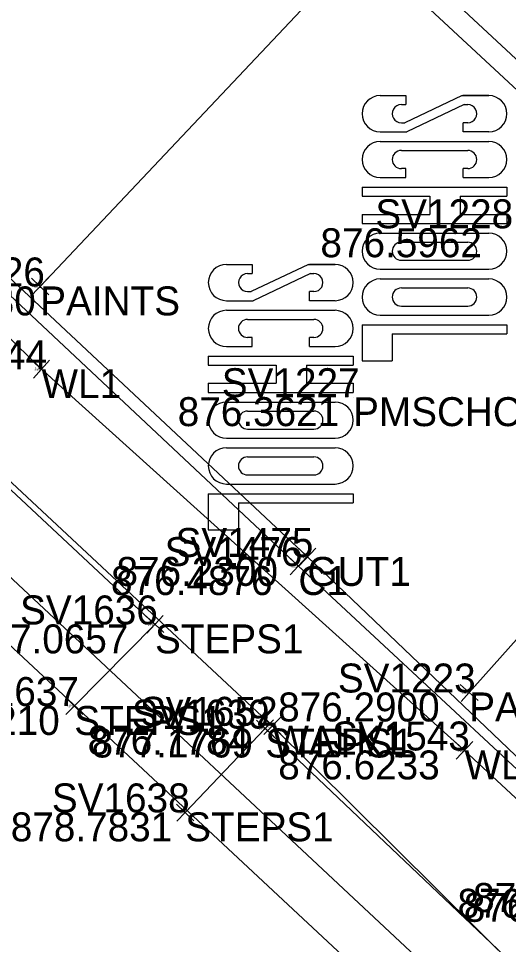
# Model space of a CAD drawing. Extents: x 1469677 to 1493262, y 375219 to 389293.
# Drawn here: x 1480273.43 to 1480293.74, y 379275.14 to 379313.52 of the extents above; entities that cross this region are included whole.
import ezdxf

# ---------------------------------------------------------------- set-up
doc = ezdxf.new("R2010")
doc.units = 0
for name, color, linetype in [('Building', 7, 'Continuous'), ('DR_X_Drive_Pipe', 7, 'Continuous'), ('DV_X_Lot_Line', 7, 'Continuous'), ('DV_X_Text', 7, 'Continuous'), ('GK_Visualization', 7, 'Continuous'), ('PNTELEV', 7, 'Continuous'), ('Property', 7, 'Continuous'), ('RD_P_Text', 7, 'Continuous'), ('RW_P_Esmt_SW', 7, 'Continuous'), ('RW_P_Esmt_TMP', 7, 'Continuous'), ('SV_X_Mon_Cells_Found', 7, 'Continuous'), ('SV_X_Text', 7, 'Continuous'), ('SV_X_Text_Elevation', 7, 'Continuous'), ('Text Street', 7, 'Continuous')]:
    doc.layers.add(name, color=color, linetype=linetype)

msp = doc.modelspace()

# ---------------------------------------------------------------- linework, layer by layer
at = {"layer": 'Building'}
msp.add_lwpolyline([(1480349.171, 379259.048), (1480326.954, 379280.06), (1480305.568, 379299.916), (1480284.393, 379319.578), (1480263.301, 379339.268), (1480242.575, 379359.213), (1480224.612, 379376.165), (1480208.191, 379391.527)], dxfattribs=at)
at = {"layer": 'DR_X_Drive_Pipe'}
msp.add_lwpolyline([(1480327.263, 379249.797), (1480312.798, 379263.799), (1480291.915, 379283.182), (1480274.385, 379298.987), (1480265.401, 379307.725), (1480264.495, 379308.458), (1480240.472, 379331.084), (1480234.677, 379335.863), (1480225.088, 379345.601), (1480208.322, 379361.342), (1480207.346, 379362.25), (1480199.528, 379369.768), (1480193.21, 379375.651), (1480182.823, 379385.139), (1480177.927, 379389.525), (1480169.423, 379398.321), (1480161.035, 379406.189), (1480144.924, 379421.019), (1480134.739, 379430.559), (1480121.485, 379441.998)], dxfattribs=at)
at = {"layer": 'DV_X_Lot_Line'}
msp.add_lwpolyline([(1480327.959, 379242.083), (1480313.163, 379256.356), (1480297.576, 379270.674), (1480283.951, 379284.205), (1480267.344, 379299.69), (1480258.509, 379307.782), (1480244.036, 379321.372), (1480229.243, 379335.021), (1480213.414, 379349.982), (1480196.806, 379366.202), (1480192.296, 379370.271), (1480186.385, 379375.802), (1480181.8, 379379.27), (1480179.258, 379381.212), (1480177.445, 379382.131), (1480174.921, 379382.868), (1480171.98, 379383.537), (1480169.491, 379383.403), (1480167.014, 379382.902), (1480162.891, 379380.83), (1480161.298, 379379.691), (1480158.915, 379377.808)], dxfattribs=at)
at = {"layer": 'PNTELEV'}
for p, q in [((1480274.675, 379302.78), (1480273.989, 379302.052)), ((1480274.696, 379302.073), (1480273.968, 379302.759)), ((1480274.332, 379302.416), (1480274.332, 379302.416)), ((1480274.757, 379298.652), (1480274.014, 379299.322)), ((1480274.05, 379298.616), (1480274.72, 379299.358)), ((1480274.385, 379298.987), (1480274.385, 379298.987)), ((1480285.771, 379290.857), (1480285.048, 379291.548)), ((1480285.064, 379290.841), (1480285.755, 379291.564)), ((1480285.399, 379290.486), (1480284.667, 379291.167)), ((1480284.693, 379290.46), (1480285.374, 379291.192)), ((1480285.409, 379291.203), (1480285.409, 379291.203)), ((1480285.033, 379290.826), (1480285.033, 379290.826)), ((1480278.723, 379288.748), (1480279.455, 379288.066)), ((1480279.43, 379288.773), (1480278.748, 379288.042)), ((1480279.089, 379288.407), (1480279.089, 379288.407)), ((1480291.737, 379285.918), (1480292.482, 379285.252)), ((1480291.776, 379285.212), (1480292.443, 379285.958)), ((1480292.11, 379285.585), (1480292.11, 379285.585)), ((1480276.098, 379284.673), (1480275.388, 379285.376)), ((1480276.095, 379285.38), (1480275.391, 379284.669)), ((1480275.743, 379285.025), (1480275.743, 379285.025)), ((1480283.297, 379284.436), (1480284.021, 379283.745)), ((1480283.314, 379283.729), (1480284.004, 379284.452)), ((1480284.306, 379283.852), (1480283.596, 379284.557)), ((1480283.599, 379283.85), (1480284.303, 379284.56)), ((1480283.659, 379284.091), (1480283.659, 379284.091)), ((1480283.951, 379284.205), (1480283.951, 379284.205)), ((1480292.282, 379282.842), (1480291.549, 379283.522)), ((1480291.575, 379282.816), (1480292.255, 379283.548)), ((1480291.915, 379283.182), (1480291.915, 379283.182)), ((1480279.979, 379280.961), (1480280.703, 379280.271)), ((1480279.996, 379280.254), (1480280.686, 379280.977)), ((1480280.341, 379280.616), (1480280.341, 379280.616))]:
    msp.add_line(p, q, dxfattribs=at)
at = {"layer": 'Property'}
for points in [[(1480263.984, 379296.161), (1480267.157, 379299.539), (1480279.089, 379288.407), (1480275.743, 379285.025)], [(1480280.341, 379280.616), (1480283.659, 379284.091), (1480295.222, 379273.109), (1480291.804, 379269.54)]]:
    msp.add_lwpolyline(points, dxfattribs=at)
at = {"layer": 'RD_P_Text'}
for points in [[(1480328.343, 379250.587), (1480312.97, 379265.236), (1480299.564, 379277.688), (1480285.409, 379291.203), (1480266.888, 379308.553), (1480264.304, 379310.926), (1480249.8, 379324.506)], [(1480327.862, 379250.385), (1480312.733, 379264.825), (1480299.577, 379277.28), (1480299.42, 379277.447), (1480285.033, 379290.826), (1480266.518, 379308.208), (1480264.058, 379310.698), (1480249.543, 379324.24)]]:
    msp.add_lwpolyline(points, dxfattribs=at)
at = {"layer": 'RW_P_Esmt_TMP'}
for p, q in [((1480288.423, 379310.327), (1480289.485, 379310.327)), ((1480291.818, 379310.327), (1480289.443, 379309.202)), ((1480289.485, 379310.327), (1480289.485, 379309.952)), ((1480291.818, 379310.327), (1480292.923, 379310.327)), ((1480292.923, 379310.327), (1480291.86, 379310.327)), ((1480289.298, 379309.952), (1480289.485, 379309.952)), ((1480291.902, 379309.952), (1480289.527, 379308.827)), ((1480291.902, 379309.952), (1480292.048, 379309.952)), ((1480289.298, 379309.202), (1480289.443, 379309.202)), ((1480292.048, 379309.202), (1480291.86, 379309.202)), ((1480291.86, 379308.827), (1480291.86, 379309.202)), ((1480288.423, 379308.827), (1480289.527, 379308.827)), ((1480292.923, 379308.827), (1480291.86, 379308.827)), ((1480288.423, 379308.427), (1480292.923, 379308.427)), ((1480289.298, 379308.052), (1480292.048, 379308.052)), ((1480289.485, 379307.302), (1480289.298, 379307.302)), ((1480289.485, 379306.927), (1480289.485, 379307.302)), ((1480291.86, 379306.927), (1480291.86, 379307.302)), ((1480292.048, 379307.302), (1480291.86, 379307.302)), ((1480288.423, 379306.927), (1480289.485, 379306.927)), ((1480291.86, 379306.927), (1480292.923, 379306.927)), ((1480287.673, 379306.527), (1480293.673, 379306.527)), ((1480287.673, 379306.527), (1480287.673, 379306.152)), ((1480293.673, 379306.527), (1480293.673, 379306.152)), ((1480287.673, 379306.152), (1480290.485, 379306.152)), ((1480290.485, 379306.152), (1480290.485, 379305.402)), ((1480291.735, 379306.152), (1480291.735, 379305.402)), ((1480291.735, 379306.152), (1480293.673, 379306.152)), ((1480287.673, 379305.402), (1480290.485, 379305.402)), ((1480287.673, 379305.402), (1480287.673, 379305.027)), ((1480291.735, 379305.402), (1480293.673, 379305.402)), ((1480293.673, 379305.402), (1480293.673, 379305.027)), ((1480287.673, 379305.027), (1480293.673, 379305.027)), ((1480287.673, 379304.827), (1480287.673, 379304.827)), ((1480293.673, 379304.827), (1480293.673, 379304.827)), ((1480288.423, 379304.627), (1480292.923, 379304.627)), ((1480289.298, 379304.252), (1480292.048, 379304.252)), ((1480282.049, 379303.326), (1480283.111, 379303.326)), ((1480285.444, 379303.326), (1480283.069, 379302.201)), ((1480283.111, 379303.326), (1480283.111, 379302.951)), ((1480285.444, 379303.326), (1480286.549, 379303.326)), ((1480286.549, 379303.326), (1480285.486, 379303.326)), ((1480289.298, 379303.502), (1480292.048, 379303.502)), ((1480282.924, 379302.951), (1480283.111, 379302.951)), ((1480285.528, 379302.951), (1480283.153, 379301.826)), ((1480285.528, 379302.951), (1480285.674, 379302.951)), ((1480288.423, 379303.127), (1480292.923, 379303.127)), ((1480288.423, 379302.727), (1480292.923, 379302.727)), ((1480282.924, 379302.201), (1480283.069, 379302.201)), ((1480285.674, 379302.201), (1480285.486, 379302.201)), ((1480285.486, 379301.826), (1480285.486, 379302.201)), ((1480289.298, 379302.352), (1480292.048, 379302.352)), ((1480282.049, 379301.826), (1480283.153, 379301.826)), ((1480286.549, 379301.826), (1480285.486, 379301.826)), ((1480282.049, 379301.426), (1480286.549, 379301.426)), ((1480288.423, 379301.227), (1480292.923, 379301.227)), ((1480289.298, 379301.602), (1480292.048, 379301.602)), ((1480282.924, 379301.051), (1480285.674, 379301.051)), ((1480287.673, 379300.827), (1480293.673, 379300.827)), ((1480287.673, 379300.827), (1480287.673, 379299.327)), ((1480293.673, 379300.827), (1480293.673, 379300.452)), ((1480283.111, 379300.301), (1480282.924, 379300.301)), ((1480283.111, 379299.926), (1480283.111, 379300.301)), ((1480285.486, 379299.926), (1480285.486, 379300.301)), ((1480285.674, 379300.301), (1480285.486, 379300.301)), ((1480288.923, 379300.452), (1480293.673, 379300.452)), ((1480288.923, 379300.452), (1480288.923, 379299.327)), ((1480282.049, 379299.926), (1480283.111, 379299.926)), ((1480285.486, 379299.926), (1480286.549, 379299.926)), ((1480281.299, 379299.526), (1480287.299, 379299.526)), ((1480281.299, 379299.526), (1480281.299, 379299.151)), ((1480287.299, 379299.526), (1480287.299, 379299.151)), ((1480287.673, 379299.327), (1480288.923, 379299.327)), ((1480281.299, 379299.151), (1480284.111, 379299.151)), ((1480284.111, 379299.151), (1480284.111, 379298.401)), ((1480285.361, 379299.151), (1480285.361, 379298.401)), ((1480285.361, 379299.151), (1480287.299, 379299.151)), ((1480281.299, 379298.401), (1480284.111, 379298.401)), ((1480281.299, 379298.401), (1480281.299, 379298.026)), ((1480285.361, 379298.401), (1480287.299, 379298.401)), ((1480287.299, 379298.401), (1480287.299, 379298.026)), ((1480281.299, 379298.026), (1480287.299, 379298.026)), ((1480281.299, 379297.826), (1480281.299, 379297.826)), ((1480287.299, 379297.826), (1480287.299, 379297.826)), ((1480282.049, 379297.626), (1480286.549, 379297.626)), ((1480282.924, 379297.251), (1480285.674, 379297.251)), ((1480282.924, 379296.501), (1480285.674, 379296.501)), ((1480282.049, 379296.126), (1480286.549, 379296.126)), ((1480282.049, 379295.726), (1480286.549, 379295.726)), ((1480282.924, 379295.351), (1480285.674, 379295.351)), ((1480282.924, 379294.601), (1480285.674, 379294.601)), ((1480282.049, 379294.226), (1480286.549, 379294.226)), ((1480281.299, 379293.826), (1480287.299, 379293.826)), ((1480281.299, 379293.826), (1480281.299, 379292.326)), ((1480287.299, 379293.826), (1480287.299, 379293.451)), ((1480282.549, 379293.451), (1480287.299, 379293.451)), ((1480282.549, 379293.451), (1480282.549, 379292.326)), ((1480281.299, 379292.326), (1480282.549, 379292.326))]:
    msp.add_line(p, q, dxfattribs=at)
for centre, radius, start, end in [((1480288.423, 379309.577), 0.75, 90, 270), ((1480292.923, 379309.577), 0.75, 270, 90), ((1480289.298, 379309.577), 0.375, 90, 270.0001), ((1480292.048, 379309.577), 0.375, 270, 90.0001), ((1480288.423, 379307.677), 0.75, 90, 269.997), ((1480292.923, 379307.677), 0.75, 270.003, 90), ((1480289.298, 379307.677), 0.375, 90, 269.997), ((1480292.048, 379307.677), 0.375, 270.003, 90), ((1480288.423, 379303.877), 0.75, 90, 269.997), ((1480292.923, 379303.877), 0.75, 270.003, 90), ((1480289.298, 379303.877), 0.375, 90, 269.997), ((1480292.048, 379303.877), 0.375, 270.003, 90), ((1480282.049, 379302.576), 0.75, 90, 270), ((1480286.549, 379302.576), 0.75, 270, 90), ((1480282.924, 379302.576), 0.375, 90, 270.0001), ((1480285.674, 379302.576), 0.375, 270, 90.0001), ((1480288.423, 379301.977), 0.75, 90, 269.997), ((1480292.923, 379301.977), 0.75, 270.003, 90), ((1480289.298, 379301.977), 0.375, 90, 269.997), ((1480292.048, 379301.977), 0.375, 270.003, 90), ((1480282.049, 379300.676), 0.75, 90, 269.997), ((1480286.549, 379300.676), 0.75, 270.003, 90), ((1480282.924, 379300.676), 0.375, 90, 269.997), ((1480285.674, 379300.676), 0.375, 270.003, 90), ((1480282.049, 379296.876), 0.75, 90, 269.997), ((1480286.549, 379296.876), 0.75, 270.003, 90), ((1480282.924, 379296.876), 0.375, 90, 269.997), ((1480285.674, 379296.876), 0.375, 270.003, 90), ((1480282.049, 379294.976), 0.75, 90, 269.997), ((1480286.549, 379294.976), 0.75, 270.003, 90), ((1480282.924, 379294.976), 0.375, 90, 269.997), ((1480285.674, 379294.976), 0.375, 270.003, 90)]:
    msp.add_arc(centre, radius, start, end, dxfattribs=at)
at = {"layer": 'SV_X_Mon_Cells_Found'}
msp.add_lwpolyline([(1477164.629, 382297.849), (1479615.888, 379904.59), (1480413.414, 379159.216)], dxfattribs=at)
at = {"layer": 'SV_X_Text'}
for points in [[(1480287.258, 379316.117), (1480274.332, 379302.416)], [(1480292.11, 379285.585), (1480304.569, 379299.538)]]:
    msp.add_lwpolyline(points, dxfattribs=at)
at = {"layer": 'SV_X_Text_Elevation'}
msp.add_line((1479636.611, 379926.284), (1480557.828, 379065.308), dxfattribs=at)
at = {"layer": 'Text Street'}
msp.add_lwpolyline([(1480285.873, 379260.463), (1480292.461, 379269.459), (1480263.894, 379296.102), (1480254.759, 379289.34)], dxfattribs=at)

# ---------------------------------------------------------------- texts
at = {"layer": 'DV_X_Text'}
for s, height, p in [('876.5962', 1.2, (1480285.944, 379303.627)), ('876.1130', 1.2, (1480267.455, 379301.216)), ('876.11', 0.06, (1480274.097, 379302.356)), ('876.47', 0.06, (1480274.103, 379298.927)), ('876.3621', 1.2, (1480280.031, 379296.626)), ('876.2300', 1.2, (1480277.492, 379290.003)), ('876.23', 0.06, (1480285.129, 379291.143)), ('876.4876', 1.2, (1480277.267, 379289.626)), ('876.49', 0.06, (1480284.751, 379290.766)), ('877.0657', 1.2, (1480271.294, 379287.207)), ('877.07', 0.06, (1480278.804, 379288.347)), ('876.2900', 1.2, (1480284.192, 379284.385)), ('876.29', 0.06, (1480291.829, 379285.525)), ('878.8210', 1.2, (1480268.45, 379283.825)), ('878.82', 0.06, (1480275.463, 379284.965)), ('876.7784', 1.2, (1480276.298, 379283.005)), ('877.1769', 1.2, (1480276.46, 379282.891)), ('877.18', 0.06, (1480283.403, 379284.031)), ('876.78', 0.06, (1480283.67, 379284.145)), ('876.6233', 1.2, (1480284.196, 379281.982)), ('876.62', 0.06, (1480291.633, 379283.122)), ('878.7831', 1.2, (1480273.111, 379279.416)), ('878.78', 0.06, (1480280.061, 379280.556)), ('876.5596', 1.2, (1480291.625, 379276.247)), ('876.4126', 1.2, (1480292.271, 379276.488)), ('876.4422', 1.2, (1480291.886, 379276.08))]:
    msp.add_text(s, height=height, dxfattribs=at).set_placement(p)
at = {"layer": 'GK_Visualization'}
for s, p in [('PAINTS', (1480274.332, 379301.216)), ('WL1', (1480274.385, 379297.787)), ('PMSCHOOL', (1480287.299, 379296.626)), ('GUT1', (1480285.409, 379290.003)), ('C1', (1480285.033, 379289.626)), ('STEPS1', (1480279.089, 379287.207)), ('PAINTS', (1480292.11, 379284.385)), ('STEPS1', (1480275.743, 379283.825)), ('STEPS1', (1480283.659, 379282.891)), ('WALK1', (1480283.951, 379283.005)), ('WL1', (1480291.915, 379281.982)), ('STEPS1', (1480280.341, 379279.416))]:
    msp.add_text(s, height=1.2, dxfattribs=at).set_placement(p)
at = {"layer": 'RW_P_Esmt_SW'}
for s, height, p in [('SV1228', 1.2, (1480288.222, 379304.827)), ('SV1226', 1.2, (1480268.815, 379302.416)), ('SV1226', 0.06, (1480274.056, 379302.416)), ('SV1544', 1.2, (1480268.906, 379298.987)), ('SV1544', 0.06, (1480274.111, 379298.987)), ('SV1227', 1.2, (1480281.857, 379297.826)), ('SV1475', 1.2, (1480279.94, 379291.203)), ('SV1476', 1.2, (1480279.488, 379290.826)), ('SV1475', 0.06, (1480285.136, 379291.203)), ('SV1476', 0.06, (1480284.756, 379290.826)), ('SV1636', 1.2, (1480273.496, 379288.407)), ('SV1636', 0.06, (1480278.809, 379288.407)), ('SV1223', 1.2, (1480286.668, 379285.585)), ('SV1637', 1.2, (1480270.226, 379285.025)), ('SV1223', 0.06, (1480291.838, 379285.585)), ('SV1639', 1.2, (1480278.132, 379284.091)), ('SV1652', 1.2, (1480278.462, 379284.205)), ('SV1637', 0.06, (1480275.467, 379285.025)), ('SV1543', 1.2, (1480286.427, 379283.182)), ('SV1639', 0.06, (1480283.383, 379284.091)), ('SV1652', 0.06, (1480283.677, 379284.205)), ('SV1543', 0.06, (1480291.641, 379283.182)), ('SV1638', 1.2, (1480274.814, 379280.616)), ('SV1638', 0.06, (1480280.065, 379280.616))]:
    msp.add_text(s, height=height, dxfattribs=at).set_placement(p)

doc.saveas('drawing.dxf')
